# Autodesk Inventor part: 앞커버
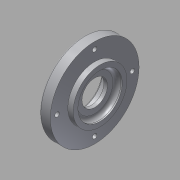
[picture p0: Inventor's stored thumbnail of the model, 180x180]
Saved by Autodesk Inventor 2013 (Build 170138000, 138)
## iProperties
Created: 2015-09
Part Number: 앞커버
Material: 알루미늄 6061
Document SubType Name: Modeling
Designer: mduedu
Density: 1 g/cm^3
Author: mduedu
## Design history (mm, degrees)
sketch "스케치1"
  geometry: L1 (-8, 67)-(-12, 67); L2 (-12, 67)-(-12, 80); L3 (-12, 80)-(-20, 80); L4 (-20, 80)-(-20, 70.5); L5 (-23, 70.5)-(-23, 56.5); L6 (-23, 56.5)-(-8, 56.5); L7 (-8, 56.5)-(-8, 67); L8 (-79.5, 39.5)-(-79.5, 54.5) reference; L9 (48.5, 54.5)-(48.5, 39.5) reference; L10 (-79.5, 47)-(48.5, 47); L11 (-20, 70.5)-(-23, 70.5); 3 further points
  constraints: 18 end point, 6 parallel, 4 midpoint, 1 horizontal, 1 perpendicular, 1 vertical alignment
  dimensions: "d0" = 15 distance between parallel lines of L7 L5; "d2" = 19 diameter of L6 L10; "d3" = 40 diameter of L1 L10; "d5" = 4 distance of L1.start L1.end; "d6" = 66 diameter of L3 L10; "d7" = 8 distance of L2.end L3.end; "d8" = 47 diameter of L4.end L10
revolve "회전1" sketch "스케치1" stored, may be unused: angle "d4" = 90 deg
sketch "스케치2"
  geometry: C1 r 33 at (0, 0) reference; 2 further points
  constraints: 1 coincident
hole "구멍1" sketch "스케치2" at (0, 0) diameter "d11" = 33; stored, may be unused: countersink angle "d15" = 90 deg, drill point angle "d17" = 0 deg; dims "d12" = 6, "d13" = 4, "d14" = 2, "d16" = 4
fillet "모깎기1" dims "d18" = 3
fillet "모깎기2" dims "d19" = 1
sketch "스케치3"
  geometry: C1 r 33 at (0, 0) reference; 2 further points
  constraints: 1 coincident
hole "구멍2" sketch "스케치3" at (0, 0) diameter "d20" = 32; stored, may be unused: countersink angle "d24" = 90 deg, drill point angle "d26" = 0 deg; dims "d21" = 6, "d22" = 4, "d23" = 2, "d25" = 8.3
fillet "모깎기3" dims "d27" = 0.3
chamfer "모따기1" distance "d28" = 0.8; stored, may be unused: second distance "d29" = 2, angle "d30" = 30 deg
sketch "스케치4" dims "d31" = 56
  geometry: C1 r 33 at (0, 0) reference; 6 further points
  constraints: 2 vertical alignment, 1 coincident, 7 other
  dimensions: "d36" = 360 deg dimension on C1.centre point (0, 28) (derived)
sketch "스케치7"
  geometry: 4 further points
hole "구멍4" sketch "스케치7" at (0, 28), (-28, 0), (28, 0), (0, -28) diameter "d48" = 3.4; stored, may be unused: countersink angle "d52" = 90 deg, drill point angle "d54" = 0 deg; dims "d49" = 6, "d50" = 6.5, "d51" = 3.4, "d53" = 8
node "솔리드1"
node "참조1"
node "참조2"
